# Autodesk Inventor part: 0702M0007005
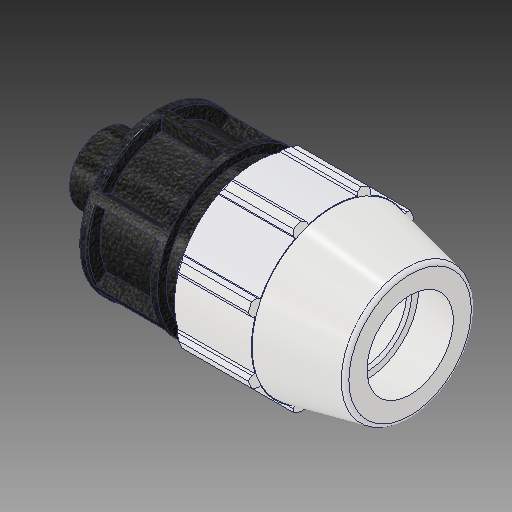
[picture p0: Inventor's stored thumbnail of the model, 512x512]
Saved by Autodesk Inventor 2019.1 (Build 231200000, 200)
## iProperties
Created: 2017-02
Part Number: 0702M0007005
Material: PVC-Piping
Description: PLASSON MALE ADAPTOR 3/4'' - 1/2''M
Document SubType Name: Modeling
Designer: KIM
Mass: 92.6774 g
Surface Area: 199.44 cm^2
Volume: 66.1981 cm^3
Density: 1.4 g/cm^3
Appearance: PTFE
Author: KIM
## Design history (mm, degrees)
derived "0702M0.ipt"
feature "Solid1::0702M0.ipt"
tag "TaggingFeature1"
body "Solid1"
other parameters: "d2" = 26.6, "d4" = 13.57086, "d5" = 23.749, "d7" = 54.102, "d8" = 40.5765, "d9" = 13.57086, "d11" = 2.71417, "d12" = 43.2816, "d13" = 120 deg, "d14" = 39.9, "d15" = 12 deg, "d16" = 48.6918, "d18" = 1.33, "d19" = 35 deg, "d20" = 17.5 deg, "d21" = 50.31486, "d23" = 0, "d25" = 360 deg, "d27" = 1.08204, "d34" = 2.7051, "d36" = 0, "d42" = 23.749, "d43" = 1.62306, "d46" = 0.798, "d49" = 71.882, "d51" = 94.996, "d52" = 17.018, "d53" = 0.532, "d55" = 360 deg, "d57" = 20.955, "d58" = 14.6685, "d59" = 18.9992, "d_" = 26.6, "E_" = 54.102, "H_" = 94.996, "l_" = 71.882, "l_2" = 17.018, "G_" = 20.955
